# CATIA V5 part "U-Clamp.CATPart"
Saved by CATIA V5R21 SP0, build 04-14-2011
Part number: U-Clamp
Bounding box of the stored display mesh (mm): x -22.987 to 22.987, y -6.35 to 6.35, z -25.4 to 28.702
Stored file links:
  D:\CATIA V5R21 E-RESOURCES\CATIA-V5R21\catia-v5r21-Prts\c13_catia_v5r21_prt\c13_catia_v5r21_figr_13-43\Part & Asm files\U-Clamp.CATPart
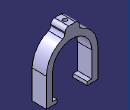
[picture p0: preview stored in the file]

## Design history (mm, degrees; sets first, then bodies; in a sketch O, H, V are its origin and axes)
Body1 (main body)
  Sketch1 on zx-plane, origin (0, 0, 0), H (-1, 0, 0), V (0, 0, 1)
    arc A1 centre (0, 0) radius 17.526 from (17.526, 0) to (-17.526, 0) ccw
    point P1 (-17.526, 0)
    point P2 (17.526, 0)
    line L1 (-17.526, 0) -> (-17.526, -22.352)
    point P3 (-17.526, -22.352)
    line L2 (-17.526, -22.352) -> (-13.462, -22.352)
    point P4 (-13.462, -22.352)
    line L3 (-13.462, -22.352) -> (-13.462, -25.4)
    point P5 (-13.462, -25.4)
    line L4 (-13.462, -25.4) -> (-22.987, -25.4)
    point P6 (-22.987, -25.4)
    line L5 (-22.987, -25.4) -> (-22.987, 0)
    point P7 (-22.987, 0)
    arc A2 centre (0, 0) radius 22.987 from (-22.987, 0) to (-6.35, 22.0925) cw
    point P9 (22.987, 0)
    point P10 (22.987, 0)
    point P11 (22.987, -25.4)
    line L6 (22.987, -25.4) -> (22.987, 0)
    point P12 (13.462, -25.4)
    line L7 (13.462, -25.4) -> (22.987, -25.4)
    point P13 (13.462, -22.352)
    line L8 (13.462, -22.352) -> (13.462, -25.4)
    point P14 (17.526, -22.352)
    line L9 (17.526, -22.352) -> (13.462, -22.352)
    point P15 (17.526, 0)
    line L10 (17.526, 0) -> (17.526, -22.352)
    line L11 (-6.35, 22.0925) -> (-6.35, 28.702)
    point P16 (-6.35, 28.702)
    line L12 (-6.35, 28.702) -> (6.35, 28.702)
    point P17 (6.35, 28.702)
    line L13 (6.35, 28.702) -> (6.35, 22.0925)
    point P18 (6.35, 22.0925)
    arc A3 centre (0, 0) radius 22.987 from (6.35, 22.0925) to (22.987, 0) cw
    radius A1 = 17.526
    distance L3 V = 13.462
    distance H L2 = 22.352
    distance H L4 = 25.4
    distance V L5 = 22.987
    distance P16 P17 = 12.7
    distance L11 V = 6.35
    distance L12 H = 28.702
    coincidence: P1 H, P2 H, P7 H, A2 P18, A2 A3, P2 P15, P9 P10
    tangency: L1 A1, A2 L5
    horizontal: L2 H, L4 H, L12 H
    vertical: L3 V, L5 V, L11 V, L13 V
    concentricity: A2 A1
    symmetry: P7 P10 V, P6 P11 V, L5 L6 V, P5 P12 V, L4 L7 V, P4 P13 V, L3 L8 V, P3 P14 V, L2 L9 V, P1 P15 V, L1 L10 V
  Pad1: profile Sketch1, direction (0, -1, 0), length 6.35, mirrored extent
  Fillet1: radius 3.302, on 4 edges
  Sketch2 on face of Pad1, origin (-0.057, 2.6412, 28.702), H (1, 0, 0), V (0, 1, 0)
    point P1 (0.057, -2.6412)
    reference intersected line E1 through (0.057, 0) direction (0, 1) from yz-plane
    reference intersected line E2 through (0, -2.6412) direction (-1, 0) from zx-plane
    coincidence: E1 P1, E2 P1
  Hole1: placed by Sketch2, at (0, 0, 28.702) direction (0, 0, -1), diameter 3.81, depth 25.4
